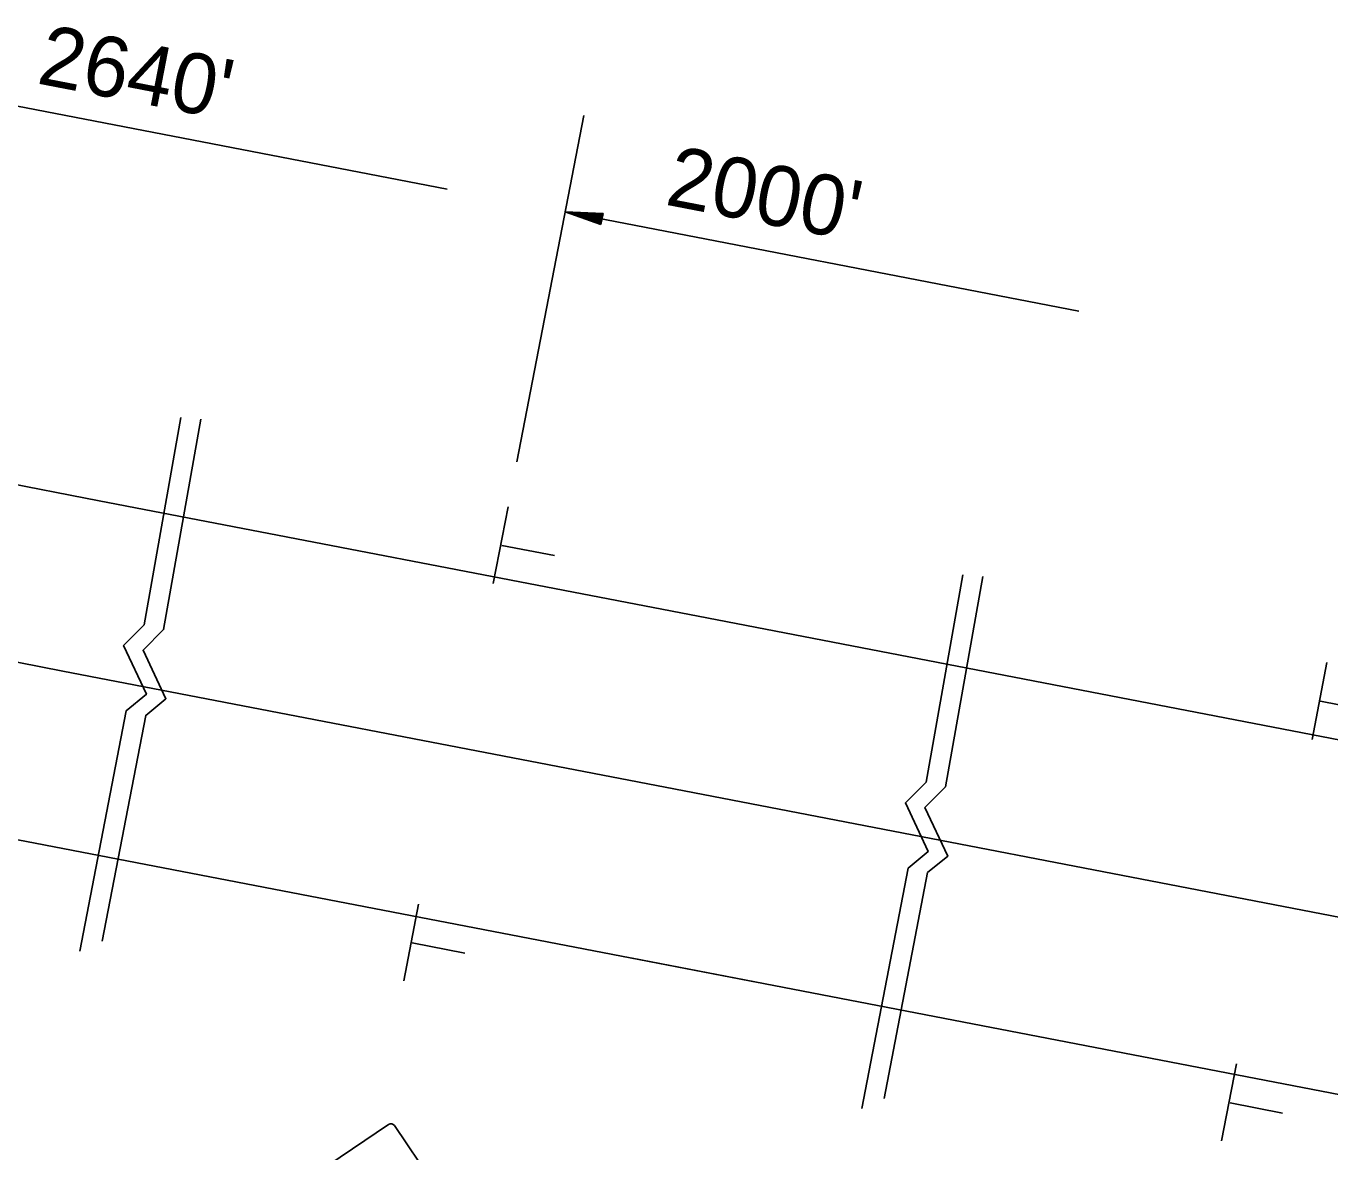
# Model space of a CAD drawing. Extents: x 606969 to 609391, y 416008 to 419486.
# Drawn here: x 607016.39 to 607029.4, y 419468.24 to 419479.48 of the extents above; entities that cross this region are included whole.
import ezdxf

# ---------------------------------------------------------------- set-up
doc = ezdxf.new("R2010")
doc.units = 0
doc.layers.add('Default', color=7, linetype='Continuous')

msp = doc.modelspace()

# ---------------------------------------------------------------- linework, layer by layer
at = {"layer": 'Default'}
for p, q in [((607015.466, 419478.844), (607020.59, 419477.855)), ((607021.951, 419478.589), (607021.284, 419475.132)), ((607021.765, 419477.628), (607026.89, 419476.638)), ((607022.123, 419477.501), (607021.765, 419477.628)), ((607022.144, 419477.612), (607021.765, 419477.628)), ((607022.125, 419477.51), (607021.827, 419477.616)), ((607022.143, 419477.603), (607021.827, 419477.616)), ((607022.141, 419477.593), (607021.89, 419477.604)), ((607022.127, 419477.52), (607021.89, 419477.604)), ((607022.128, 419477.529), (607021.952, 419477.592)), ((607022.139, 419477.584), (607021.952, 419477.592)), ((607022.123, 419477.501), (607022.144, 419477.612)), ((607022.137, 419477.575), (607022.014, 419477.58)), ((607022.13, 419477.539), (607022.014, 419477.58)), ((607022.135, 419477.565), (607022.075, 419477.568)), ((607022.132, 419477.548), (607022.075, 419477.568)), ((607011.033, 419475.919), (607017.118, 419474.744)), ((607017.118, 419474.744), (607023.092, 419473.591)), ((607021.049, 419473.917), (607021.197, 419474.685)), ((607010.748, 419474.203), (607016.755, 419473.044)), ((607021.134, 419474.297), (607021.659, 419474.196)), ((607023.092, 419473.591), (607031.596, 419471.95)), ((607016.755, 419473.044), (607022.763, 419471.884)), ((607029.217, 419472.362), (607029.365, 419473.13)), ((607029.302, 419472.742), (607029.826, 419472.641)), ((607010.464, 419472.488), (607016.392, 419471.343)), ((607022.763, 419471.884), (607031.266, 419470.243)), ((607016.392, 419471.343), (607023.692, 419469.934)), ((607020.155, 419469.95), (607020.303, 419470.718)), ((607020.24, 419470.33), (607020.764, 419470.229)), ((607022.433, 419470.177), (607031.837, 419468.362)), ((607028.314, 419468.354), (607028.463, 419469.122)), ((607028.4, 419468.734), (607028.924, 419468.632)), ((607017.237, 419466.647), (607020.003, 419468.518)), ((607020.063, 419468.507), (607021.934, 419465.74))]:
    msp.add_line(p, q, dxfattribs=at)
for points in [[(607017.933, 419475.576), (607017.565, 419473.504), (607017.36, 419473.298), (607017.589, 419472.813), (607017.387, 419472.648), (607016.923, 419470.247)], [(607018.132, 419475.557), (607017.76, 419473.458), (607017.555, 419473.252), (607017.783, 419472.767), (607017.582, 419472.602), (607017.146, 419470.347)], [(607025.733, 419474.006), (607025.366, 419471.934), (607025.16, 419471.728), (607025.389, 419471.243), (607025.188, 419471.078), (607024.724, 419468.677)], [(607025.932, 419473.987), (607025.56, 419471.888), (607025.355, 419471.682), (607025.584, 419471.197), (607025.382, 419471.032), (607024.947, 419468.777)]]:
    msp.add_lwpolyline(points, dxfattribs=at)
msp.add_arc((607020.027, 419468.483), 0.0428, 34.0745, 124.0744, dxfattribs=at)

# ---------------------------------------------------------------- texts
for s, p in [("2640'", (607016.482, 419478.913)), ("2000'", (607022.751, 419477.703))]:
    msp.add_text(s, height=0.6, rotation=349.0745, dxfattribs=at).set_placement(p)

doc.saveas('drawing.dxf')
